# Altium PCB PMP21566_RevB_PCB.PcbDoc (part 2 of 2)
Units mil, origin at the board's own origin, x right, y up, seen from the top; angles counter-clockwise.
Board outline 4339 x 2011 mil, 4 copper layers (Top Layer1, Layer2, Layer3, Bottom Layer4), stack 60.4 mil thick; 97 components, 43 nets, 239 pads, 687 vias.
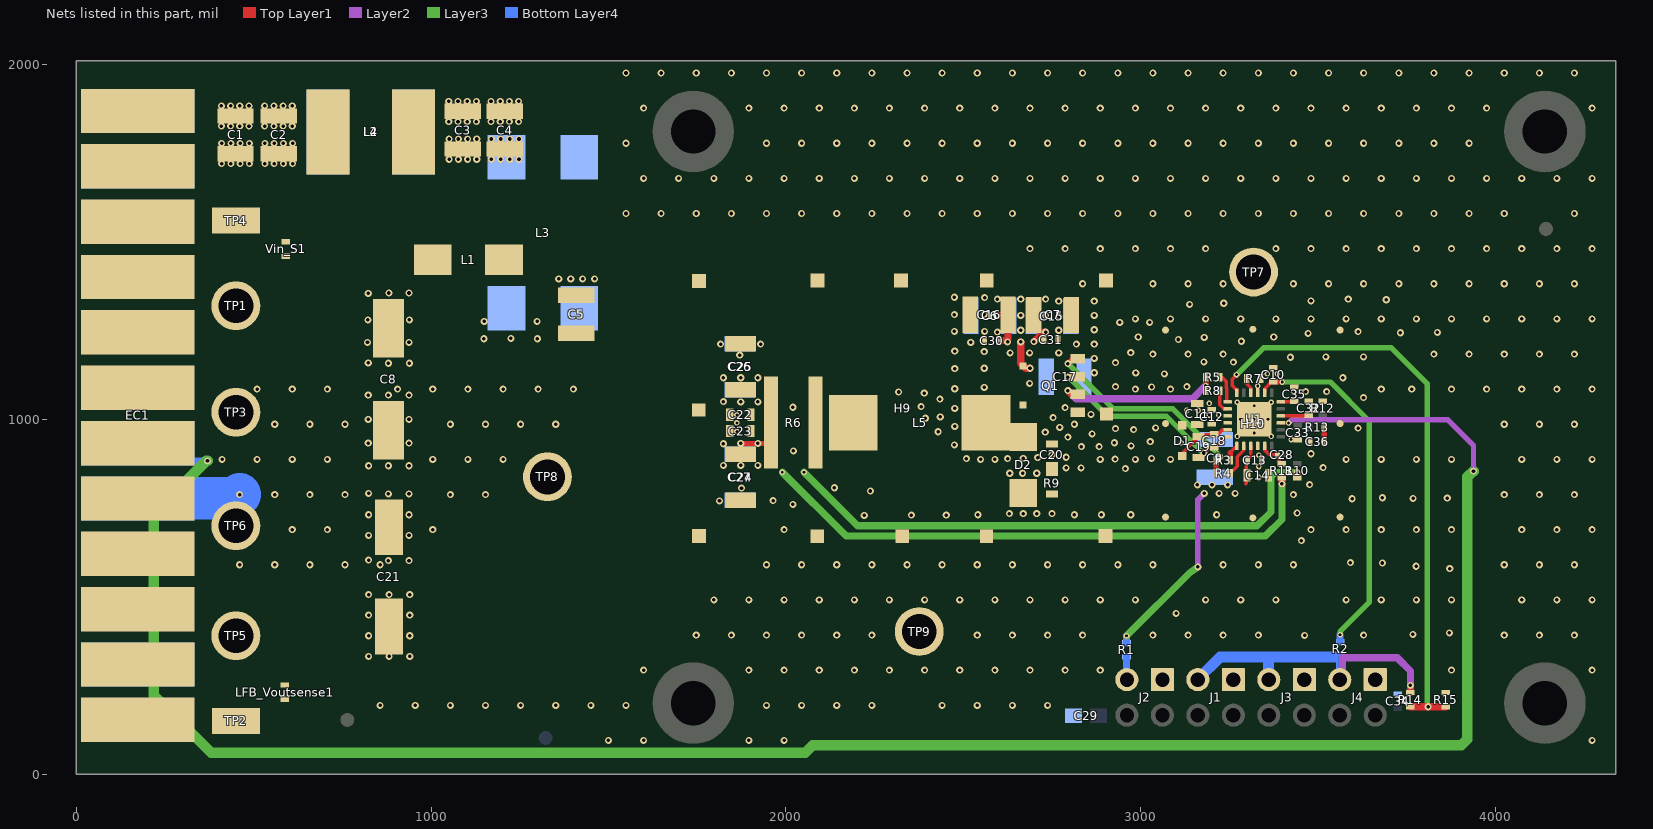
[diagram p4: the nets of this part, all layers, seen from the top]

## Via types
v1: diameter 20, hole 10, Top Layer1 to Bottom Layer4, tented both sides, 647 vias
v2: diameter 16, hole 8, Top Layer1 to Bottom Layer4, tented both sides, 35 vias
v3: diameter 19.68, hole 7.87, Top Layer1 to Bottom Layer4, 5 vias

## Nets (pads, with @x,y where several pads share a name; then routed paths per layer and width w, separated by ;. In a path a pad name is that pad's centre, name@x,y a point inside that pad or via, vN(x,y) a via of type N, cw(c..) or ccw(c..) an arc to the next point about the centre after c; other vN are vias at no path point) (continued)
GND: C5.2 C6.2 C7.2 C8.2 C9.2 C10.1 C11.2 C12.1 C13.2 C14.2 C15.2 C16.2 C17.2 C21.2 C22.2 C23.2 C24.2 C25.2 C26.2 C27.2 C29.2 C30.2 C31.2 C32.2 C33.2 C34.1 C35.2 C36.2 D2.2 EC1.5 EC1.D EC1.E EC1.F EC1.H H9.1 H10.1 J1.1 J2.1 J3.1 J4.1 L3.3 Q1.1 R7.2 R9.1 R12.1 R15.2 TP3.1 TP6.1 TP7.1 TP8.1 TP9.1 U1.3 U1.9 U1.16 U1.25@3320,1000 | length 292.1
  Bottom Layer4 w120: EC1.5@173,777 449.5,777 v1(460.5,788)
  other v1: 1500,95 1599,95 1896,95 1995,95 4272,95 856.5,194 955.5,194 1054.5,194 1153.5,194 1252.5,194 1351.5,194 1450.5,194 1549.5,194 1945.5,194 2044.5,194 2143.5,194 2242.5,194 2440.5,194 2539.5,194 2638.5,194 2737.5,194 1599,293 1896,293 1995,293 2094,293 2193,293 2292,293 2391,293 2490,293 2589,293 2688,293 2787,293 2886,293 3876,293 4272,293 3462,391 1747.5,392 1846.5,392 1945.5,392 2044.5,392 2143.5,392 2242.5,392 2539.5,392 2638.5,392 2737.5,392 2836.5,392 3034.5,392 3133.5,392 3232.5,392 3331.5,392 3628.5,392 4024.5,392 4123.5,392 4222.5,392 3767,394 3870,398 3100,453 1797,491 1896,491 1995,491 2094,491 2193,491 2292,491 2391,491 2490,491 2589,491 2688,491 2787,491 2886,491 2985,491 3183,491 3282,491 3381,491 3579,491 3678,491 3777,491 3876,491 4074,491 4173,491 4272,491 3871,579 3776,586 460.5,590 559.5,590 658.5,590 757.5,590 856.5,590 1945.5,590 2044.5,590 2143.5,590 2242.5,590 2341.5,590 2440.5,590 2539.5,590 2638.5,590 2737.5,590 2836.5,590 2935.5,590 3034.5,590 3232.5,590 3331.5,590 3430.5,590 4024.5,590 4123.5,590 4222.5,590 3681,595 3591,596 880,602 938,602 824,603 3453,658 824,673 938,673 609,689 708,689 1005,689 1995,689 3480,689 3579,689 3678,689 3777,689 3876,689 4074,689 4173,689 4272,689 2221,729 2354,730 2452,730 824,731 938,731 2541,731 2813,731 2889,731 2972,731 3214,731 2630,734 2669,734 2707,734 2750,734 3441,736 2020,760 1813,770 1964,771 3596,776 3768,777 3864,778 3681,779 559.5,788 658.5,788 757.5,788 1054.5,788 1153.5,788 3430.5,788 4024.5,788 4123.5,788 4222.5,788 880,790 938,790 824,791 2238,798 1875,806 2137,807 3476,816 2631,848 2667,848 2707,848 2957,861 2790,863 2832,863 3514,864 824,869 880,869 938,869 411,887 510,887 609,887 708,887 1005,887 1104,887 1203,887 2549,887 2589,887 2886,887 2985,887 3084,887 3579,887 3678,887 3777,887 3876,887 4074,887 4173,887 4272,887 2928,888 2509,889 2625,889 2669,890 3031,890 2710,892 2790,893 2750,900 3480,903 2021,911 2833,923 2883,923 2973,925 2475,928 823,933 938,933 2926,934 3027,937 2795,950 2863,959 2731,964 2429,965 2980,971 2929,974 3613,975 3042,976 2772,977 2476,980 559.5,986 658.5,986 757.5,986 1054.5,986 1153.5,986 1252.5,986 1351.5,986 2813,986 4024.5,986 4123.5,986 4222.5,986 823,1000 938,1000 2393,1003 2753,1005 2435,1007 2860,1014 2476,1031 2787,1033 2020,1034 2381,1036 2434,1057 3628,1061 823,1068 880,1068 938,1068 2390,1074 2318,1077 3465,1078 3524,1078 510,1085 609,1085 708,1085 906,1085 1005,1085 1104,1085 1203,1085 1302,1085 1401,1085 2985,1085 3084,1085 3678,1085 3764,1085 3876,1085 3975,1085 4074,1085 4173,1085 4272,1085 2476,1086 2559,1090 3031,1091 2929,1092 3130,1092 3570,1117 3067,1128 2869,1131.33 2986,1131 2476,1143 2559,1144 2929,1160 3261,1161 3178,1162 2869,1171.67 3422,1175 3522,1176 3628,1176 1870,1181 3034.5,1184 3133.5,1184 3232.5,1184 3826.5,1184 3925.5,1184 4024.5,1184 4123.5,1184 4222.5,1184 2769,1187 2972,1188 2559,1191 2476,1192 1816,1212 1929,1212 2819,1212 2869,1212 2521,1217 3284,1220 3106,1225 1149,1227 1300,1227 1225,1228 3179,1231 2993,1232 3375,1232 3472,1242 3732,1244 3836,1245 3613,1247 2475,1248 2560,1248 2769,1251 2869,1252.33 2941,1273 3025,1273 1150,1276 1299,1276 2985,1283 3084,1283 3183,1283 3282,1283 3381,1283 3480,1283 3579,1283 3678,1283 3777,1283 3876,1283 3975,1283 4074,1283 4173,1283 4272,1283 2769,1290 2869,1292.67 2475,1295 2559,1296 3138,1324 3234,1327 2769,1333 2869,1333 3480,1334 3692,1337 3585,1339 2560,1343 2475,1344 2836.5,1382 3034.5,1382 3133.5,1382 3232.5,1382 3430.5,1382 3529.5,1382 3628.5,1382 3727.5,1382 3826.5,1382 3925.5,1382 4024.5,1382 4123.5,1382 4222.5,1382 2688,1481 2787,1481 2886,1481 2985,1481 3084,1481 3183,1481 3381,1481 3480,1481 3579,1481 3678,1481 3777,1481 3876,1481 3975,1481 4074,1481 4173,1481 4272,1481 1549.5,1580 1648.5,1580 1747.5,1580 1846.5,1580 1945.5,1580 2044.5,1580 2143.5,1580 2242.5,1580 2341.5,1580 2440.5,1580 2539.5,1580 2638.5,1580 2737.5,1580 2836.5,1580 2935.5,1580 3034.5,1580 3133.5,1580 3232.5,1580 3331.5,1580 3430.5,1580 3529.5,1580 3628.5,1580 3727.5,1580 3826.5,1580 3925.5,1580 4024.5,1580 4222.5,1580 1599,1679 1698,1679 1797,1679 1896,1679 1995,1679 2094,1679 2193,1679 2292,1679 2391,1679 2490,1679 2589,1679 2688,1679 2787,1679 2886,1679 2985,1679 3084,1679 3183,1679 3282,1679 3381,1679 3480,1679 3579,1679 3678,1679 3777,1679 3876,1679 3975,1679 4074,1679 4173,1679 4272,1679 1549.5,1778 1945.5,1778 2044.5,1778 2143.5,1778 2242.5,1778 2341.5,1778 2440.5,1778 2539.5,1778 2638.5,1778 2737.5,1778 2836.5,1778 2935.5,1778 3034.5,1778 3133.5,1778 3232.5,1778 3331.5,1778 3430.5,1778 3529.5,1778 3628.5,1778 3727.5,1778 3826.5,1778 3925.5,1778 1599,1877 1896,1877 1995,1877 2094,1877 2193,1877 2292,1877 2391,1877 2490,1877 2589,1877 2688,1877 2787,1877 2886,1877 2985,1877 3084,1877 3183,1877 3282,1877 3381,1877 3480,1877 3579,1877 3678,1877 3777,1877 3876,1877 3975,1877 4272,1877 1549.5,1976 1648.5,1976 1747.5,1976 1846.5,1976 1945.5,1976 2044.5,1976 2143.5,1976 2242.5,1976 2341.5,1976 2440.5,1976 2539.5,1976 2638.5,1976 2737.5,1976 2836.5,1976 2935.5,1976 3034.5,1976 3133.5,1976 3232.5,1976 3331.5,1976 3430.5,1976 3529.5,1976 3628.5,1976 3727.5,1976 3826.5,1976 3925.5,1976 4024.5,1976 4123.5,1976 4222.5,1976
  other v2: 3333,836 3333,867 3333,899 3114,934 3424,943 3272,952 3368,952 3443,957 1862,966 1862,990 1862,1012 3193,1012 3220,1012 3130,1025 3162,1025 3193,1045 3272,1048 3368,1048 3431,1078 3330,1094 3357,1128 3385,1128
  other v3: 3320,961.61 3281.61,1000 3320,1000 3358.39,1000 3320,1038.39
Gnd_EMI: C1.2 C2.1 EC1.11 EC1.12 L2.1
  other v1: 410,1720.49 436,1720.49 462,1720.49 488,1720.49 410,1777.49 436,1777.49 462,1777.49 488,1777.49 531,1826.49 557,1826.49 583,1826.49 609,1826.49 531,1883.49 557,1883.49 583,1883.49 609,1883.49
HB: C18.1 C19.2 D1.1 U1.11 | length 164
  Top Layer1 w10: D1.1@3117,895.69 3117,904 3170,957 3217,957 3230.47,970.47 U1.11@3245.2,970.47
HO: R3.1 U1.13 | length 47
  Top Layer1 w10: 3252,906.41 U1.13@3270.79,925.2
  Top Layer1 w15: R3.1@3252,886 3252,906.41
HOL: R4.1 U1.14 | length 93.1
  Top Layer1 w10: R4.1@3252,848 3272,868 3272,894.63 3290.47,913.1 U1.14@3290.47,925.2
HS: Q1.4 R3.2 R4.2 | length 629
  Top Layer1 w15: v1(2795,1157) 2808.26,1170.26 Q1.4@2822.87,1170.26 ; R4.2@3212,848 R3.2@3212,885 3217,885 v2(3226,894) ; R3.2@3212,886 R3.2@3212,887
  Layer3 w15: v1(2795,1157) 2922,1030 3090,1030 v2(3226,894)
LO: R8.1 U1.8 | length 60.6
  Top Layer1 w10: R8.1@3222.39,1074 3222.39,1040.89 3233.75,1029.53 U1.8@3245.2,1029.53
LOL: R5.1 U1.7 | length 81.7
  Top Layer1 w10: R5.1@3223,1117 3231,1117 3241.5,1106.5 3241.5,1089 3242,1088.5 3242,1052.41 U1.7@3245.2,1049.21
LS: Q1.2 R5.2 R8.2 | length 484.2
  Top Layer1 w15: R8.2@3183,1078 R8.2@3183,1080 v2(3183,1095) R5.2@3183,1117
  Top Layer1 w20: v1(2795,1081) 2805.74,1070.26 Q1.2@2822.87,1070.26
  Layer2 w20: v1(2795,1081) 2818,1058 3146,1058 v2(3183,1095)
NetC3_1: C3.1 C4.2 L2.2 L3.2
  other v1: 1170,1733 1196,1733 1222,1733 1248,1733 1170,1790 1196,1790 1222,1790 1248,1790 1050,1839 1076,1839 1102,1839 1128,1839 1050,1896 1076,1896 1102,1896 1128,1896
NetC3_2: C3.2 C4.1 L3.1 L4.2
  other v1: 1051,1733 1077,1733 1103,1733 1129,1733 1051,1790 1077,1790 1103,1790 1129,1790 1169,1839 1195,1839 1221,1839 1247,1839 1169,1896 1195,1896 1221,1896 1247,1896
NetC5_1: C5.1 L1.1 L3.4 | length 20.9
  Top Layer1 w10: C5.1@1388.15,1349.15 C5.1@1409,1349.15
  other v1: 1360,1396 1393.67,1396 1427.33,1396 1461,1396
NetC20_2: C20.2 R9.2
NetC36_1: C36.1 R13.1 | length 40
  Top Layer1 w15: C36.1@3517,937 R13.1@3517,977
NetL5_2: L5.2 R6.1 R10.1 | length 1636.7
  Top Layer1 w15: R6.1@2083.99,937.99 R6.1@2083.99,991
  Top Layer1 w20: R10.1@3441,839 v1(3441,850)
  Layer3 w20: v2(2051,851) 2202,700 3328,700 3367,739 3367,838 3379,850 v1(3441,850)
OSC: R14.1 R15.1 U1.6 | length 1686.3
  Top Layer1 w10: v2(3270,1126) 3270,1125 3258,1113 3258,1095.13 3268.13,1085 3269.1,1085 3270.79,1083.31 U1.6@3270.79,1074.8 U1.6@3270.79,1073.09
  Top Layer1 w20: R14.1@3760,190 v1(3810,190) R15.1@3860,190
  Layer3 w15: v2(3270,1126) 3271,1126 3347,1202 3706,1202 3808,1100 3808,192 v1(3810,190)
PG: EC1.6 U1.21 | length 6130.4
  Top Layer1 w10: U1.21@3394.8,990.16 3416.84,990.16 v2(3417,990)
  Layer2 w15: v2(3417,990) 3426,999 3865,999 3938,926 v1(3938,854)
  Layer3 w30: v1(370,883) 367,883 219,735 219,222 381,60 2055,60 2076,81 3903,81 3920,98 3920,838 v1(3938,854)
  Bottom Layer4 w20: EC1.6@182.76,933.04 232.79,883 v1(370,883)
RES: C35.1 U1.24 | length 36.2
  Top Layer1 w10: U1.24@3394.8,1049.21 C35.1@3431,1049.21
RT: R7.1 U1.4 | length 44.8
  Top Layer1 w10: R7.1@3299,1115 3299,1100.35 3310.16,1089.2 U1.4@3310.16,1074.8
SoftStart: C32.1 U1.22 | length 78.7
  Top Layer1 w10: U1.22@3394.8,1009.84 3471.84,1009.84 C32.1@3473,1011
SW: C18.2 C19.1 C20.1 D2.1 L5.1 Q1.3 Q1.6 U1.12 | length 578.2
  Top Layer1 w10: C18.2@3207,919 3238.79,950.79 U1.12@3245.2,950.79
  Top Layer1 w12: C19.1@3163,892 3165,892 v1(3178,905) 3192,919 C18.2@3207,919
  Layer3 w15: v1(2795,1119) 2797,1119 2907,1009 3072,1009 3176,905 v1(3178,905)
VCC: C11.1 C12.2 D1.2 U1.10
VDDA: C10.2 R2.2 U1.2 | length 1015.8
  Top Layer1 w10: U1.2@3349.53,1074.8 3349.53,1086.25 3368.27,1105 C10.2@3371,1105
  Top Layer1 w15: C10.2@3371,1105 v2(3399,1105)
  Layer3 w15: v2(3399,1105) 3535,1105 3644,996 3644,484.23 3562,402.23 v2(3562,393)
  Bottom Layer4 w20: R2.2@3562,373 v2(3562,393)
VDDA_R100K: J1.3 J3.3 J4.3 R2.1 R14.2 | length 889.1
  Top Layer1 w20: R14.2@3760,230 v1(3760,250)
  Layer2 w20: J4.3@3561.07,266.25 3568,273.18 3568,328 3723,328 3760,291 v1(3760,250)
  Layer3 w20: J4.3@3561.07,266.25 J4.3@3561.07,269.07
  Bottom Layer4 w20: J1.3@3161.07,266.25 J1.3@3161.07,267.07 ; J4.3@3561.07,266.25 R2.1@3561.07,330
  Bottom Layer4 w30: J1.3@3161.07,267.07 3224,330 3360,330 ; J3.3@3360,267.32 3360,330 ; R2.1@3561.07,330 3360,330
VIN: C6.1 C7.1 C8.1 C9.1 C13.1 C14.1 C15.1 C16.1 C17.1 C30.1 C31.1 EC1.J EC1.K L1.2 Q1.5 R1.2 TP1.1 U1.15 Vin_S1.2 | length 891.9
  Top Layer1 w10: 3296,818 3298,820 3298,884 3310.16,896.16 U1.15@3310.16,925.2
  Top Layer1 w20: v1(2595,1293) 2624.15,1293 C16.1@2626.15,1295 2626.15,1227.15 2621,1222 C30.1@2600,1222 ; v1(2662,1218) 2662,1157.11 Q1.5@2668.73,1150.38 2675.11,1144 v1(2688,1144) ; v1(2699,1219) 2726,1246 v1(2732,1246)
  Layer2 w16: v1(3161,584) 3161,773 v1(3179,791)
  Layer3 w20: v2(2960,390) 3137.31,567.31 v1(3161,584)
  Bottom Layer4 w20: R1.2@2960,370 v2(2960,390)
  other v1: 3221,791 3266,791 3160,815 3201,815 3245,815 2687,1101 880,1158 939,1158 823,1159 2632,1187 2687,1187 821,1217 938,1217 2625,1218 2596,1246 2662,1251 822,1280 939,1280 2662,1293 2732,1293 2596,1339 2662,1339 2732,1339 823,1355 881,1356 938,1356
Vin_EMI: C1.1 C2.2 EC1.M EC1.N L4.1
  other v1: 532,1720.49 558,1720.49 584,1720.49 610,1720.49 532,1777.49 558,1777.49 584,1777.49 610,1777.49 409,1826.49 435,1826.49 461,1826.49 487,1826.49 409,1883.49 435,1883.49 461,1883.49 487,1883.49
VIN_R100K: J2.3 R1.1 | length 70
  Bottom Layer4 w20: J2.3@2960,260 R1.1@2960,330
VINSENSE: EC1.L TP4.1 Vin_S1.1
Vo_IC: C28.2 R11.2 U1.17 | length 85.1
  Top Layer1 w10: U1.17@3349.53,925.2 3349.53,913.53 3363.06,900 3388.4,900 3388.98,899.42 3388.98,884.02 R11.2@3398,875
VOUT: C21.1 C22.1 C23.1 C24.1 C25.1 C26.1 C27.1 EC1.2 EC1.B EC1.C LFB_Voutsense1.1 R6.2 R11.1 TP5.1 | length 1706
  Top Layer1 w15: v1(1873,932) R6.2@1964,932
  Top Layer1 w20: v1(3398,818) R11.1@3398,831
  Layer3 w20: v2(1990,851) 2170,671 3351,671 3398,718 v1(3398,818)
  other v1: 824,332 882,332 940,332 824,390 940,390 824,448 940,448 824,506 882,506 940,506 1824,870 1873,870 1921,870 1824,931 1921,932 1873,1049 1921,1049 1824,1050 1824,1117 1873,1117 1921,1117
VOUTSENSE: EC1.A LFB_Voutsense1.2 TP2.1
pads on no net: FID1.1 FID2.1 FID3.1 FID4.1 H1.0 H2.0 H3.0 H4.0 H5.1 H6.1 H7.1 H8.1 LBL1.0 U1.25@3294.8,974.8 U1.25@3294.8,1025.2 U1.25@3345.2,974.8 U1.25@3345.2,1025.2

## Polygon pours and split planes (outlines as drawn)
VIN on Top Layer1 "VIN_L01_P100" (solid, pour order 100): 254,1465 694,1465 695,1466 694,1467 694,1622 1058,1622 1060,1620 1060,1157 254,1157
GND on Top Layer1 "GND_L01_P096" (solid, remove dead copper, pour order 96): 4324,2010 1538,2010 1525,1997 1525,-1 4322,-1 4324,1
VINSENSE on Top Layer1 "VINSENSE_L01_P088" (solid, remove dead copper, pour order 88): 330,1620 651,1620 651,1493 330,1493
GND on Top Layer1 "GND_L01_P084" (solid, remove dead copper, pour order 84): 253,1145 1567,1145 1567,0 831,0 831,559 253,559
VOUT on Top Layer1 "VOUT_L01_P032" (solid, remove dead copper, pour order 32): 1999.82,943 1813.83,943 1813.82,839 1999.82,839
VOUT on Top Layer1 "VOUT_L01_P034" (solid, remove dead copper, pour order 34): 2000,1142 1814,1142 1814,1038 2000,1038
NetL5_2 on Top Layer1 "NETL5_2_L01_P040" (solid, remove dead copper, pour order 40): 2040,1142 2040,839 2275.31,839 2275.31,1142
VOUT on Top Layer1 "VOUT_L01_P044" (solid, remove dead copper, pour order 44): 1878,1142 2000,1142 2000,840 1878,840
Vin_EMI on Top Layer1 "VIN_EMI_L01_P066" (solid, remove dead copper, pour order 66): 520,1790 770,1790 770,1650 520,1650
Vin_EMI on Top Layer1 "VIN_EMI_L01_P064" (solid, remove dead copper, pour order 64): 310,1930 500,1930 500,1820 310,1820
Vin_EMI on Top Layer1 "VIN_EMI_L01_P048" (solid, remove dead copper, pour order 48): 30,1930 390,1930 390,1650 30,1650
SW on Top Layer1 "SW_L01_P056" (solid, remove dead copper, pour order 56): 2828.98,1101.26 2828.98,1139.42 2758.76,1139.42 2748.98,1131.26 2748.98,1101.26 2585.07,1101.26 2585.07,981.26 2686.4,981.26 2788.98,1055.79 2788.98,1101.26
VIN on Top Layer1 "VIN_L01_P050" (solid, remove dead copper, pour order 50): 2585,1131.26 2742,1131.26 2742,1349 2585,1349
Gnd_EMI on Top Layer1 "GND_EMI_L01_P072" (solid, remove dead copper, pour order 72): 630,1930 390,1930 390,1650 630,1650
NetC3_1 on Top Layer1 "NETC3_1_L01_P052" (solid, remove dead copper, pour order 52): 1040,1930 1040,1690 1140,1690 1140,1930
NetC3_1 on Top Layer1 "NETC3_1_L01_P076" (solid, remove dead copper, pour order 76): 1260,1930 1040,1930 1040,1690 1260,1690
VCC on Top Layer1 "VCC_L01_P046" (solid, pour order 46): 3255,995 3106,995 3106,971 3255,971
VIN on Top Layer1 "VIN_L01_P008" (solid, pour order 8): 3315,801 3263,801 3263,880.84 3315,941.91
VIN on Top Layer1 "VIN_L01_P090" (solid, pour order 90): 3315,828 3150,828 3150,778 3270.49,778 3315,801
GND on Top Layer1 "GND_L01_P104" (solid, remove dead copper, pour order 104): 1561,1063 1561,1287 1031,1287 1031,1063
NetC5_1 on Top Layer1 "NETC5_1_L01_P106" (solid, pour order 106): 1140,1595 1480,1595 1480,1305 1140,1305
GND on Layer2 "GND_L02_P098" (solid, pour order 98): 1644,1627 42,1627 42,0 1644,0
GND on Layer2 "GND_L02_P078" (solid, remove dead copper, pour order 78): 1539,2011 4294,2011 4294,0 1539,0
Vin_EMI on Layer2 "VIN_EMI_L02_P060" (solid, remove dead copper, pour order 60): 630,1650 390,1650 390,1930 630,1930
NetC3_2 on Layer2 "NETC3_2_L02_P058" (solid, remove dead copper, pour order 58): 1030,1930 1030,1690 1260,1690 1260,1930
VIN on Layer3 "VIN_L03_P094" (solid, pour order 94): 347,1493 347,1110 1540,1110 1540,1493
VIN on Layer3 "VIN_L03_P092" (solid, pour order 92): 350,1462 350,1426 350,1181 995,1181 995,1462
GND on Layer3 "GND_L03_P080" (solid, pour order 80): 1529,2010 4331,2010 4339,2002 4339,19 1529,19
Gnd_EMI on Layer3 "GND_EMI_L03_P068" (solid, remove dead copper, pour order 68): 630,1930 390,1930 390,1650 630,1650
NetC3_1 on Layer3 "NETC3_1_L03_P074" (solid, remove dead copper, pour order 74): 1040,1930 1260,1930 1260,1690 1040,1690
VOUT on Layer3 "VOUT_L03_P012" (solid, remove dead copper, pour order 12): 1942,1138 1942,688 1496,242 329,242 329,564 964,564 1538,1138
VIN on Layer3 "VIN_L03_P022" (solid, pour order 22): 2750,1365 2750,1100 1975.37,1100 1713.91,1494 2621,1494
VIN on Layer3 "VIN_L03_P024" (solid, pour order 24): 2329,1493 1493,1493 1493,1148 1783,1148 1783.78,1148.78 2329,1150.26
VIN on Layer3 "VIN_L03_P002" (solid, pour order 2): 1947,1417 2523,841 3319,841 3319,752 2340,752 1947,1145
GND on Layer3 "GND_L03_P110" (solid, remove dead copper, pour order 110): 1415.01,1095 347,1095 347,571 1411.53,571
VOUT on Bottom Layer4 "VOUT_L04_P026" (solid, remove dead copper, pour order 26): 1010,527 1010,243 357,243 357,527
VOUT on Bottom Layer4 "VOUT_L04_P028" (solid, remove dead copper, pour order 28): 1010,371 1010,246 309,246 309,371
EN on Bottom Layer4 "EN_L04_P086" (solid, remove dead copper, pour order 86): 322,1619 402,1619 402,1494 322,1494
GND on Bottom Layer4 "GND_L04_P082" (solid, remove dead copper, pour order 82): 1662,1627 356,1627 356,559 1662,559
VOUT on Bottom Layer4 "VOUT_L04_P030" (solid, remove dead copper, pour order 30): 1931.88,943 1813,943 1813,858 1931.88,858
VOUT on Bottom Layer4 "VOUT_L04_P036" (solid, remove dead copper, pour order 36): 1931.73,1129 1814,1129 1814,1038 1931.73,1038
GND on Bottom Layer4 "GND_L04_P062" (solid, remove dead copper, pour order 62): 1530,0 4308.98,0 4308.98,1996 1530,1996
Vin_EMI on Bottom Layer4 "VIN_EMI_L04_P070" (solid, remove dead copper, pour order 70): 630,1650 390,1650 390,1930 630,1930
VIN on Bottom Layer4 "VIN_L04_P038" (solid, remove dead copper, pour order 38): 2751,1349 2577.93,1349 2577.93,1246.47 2681.56,1069 2751,1069
VIN on Bottom Layer4 "VIN_L04_P006" (solid, remove dead copper, pour order 6): 3259.41,856 3280.04,779.55 3149,779.55 3149,856
GND on Bottom Layer4 "GND_L04_P102" (solid, pour order 102): 359,660.66 359,0 1595,0 1595,660.66
NetC3_2 on Bottom Layer4 "NETC3_2_L04_P108" (solid, remove dead copper, pour order 108): 1262,1930 1025,1930 1025,1689 1263.85,1689

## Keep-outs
Keep-Out Layer:
  text ".Layer_Name" at 195,-1308.49 h60

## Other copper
Top Layer1:
  rectangle net NetC3_2: 980,1690 1140,1800
  region net SW: 2758.98,1071.26 2628.98,1071.26 2628.98,1041.26 2758.98,1041.26
  region net SW: 2638.98,1091.26 2585.07,1091.26 2585.07,1051.26 2638.98,1051.26
  region net VIN: 2668.98,1111.26 2585.07,1111.26 2585.07,1101.26 2668.98,1101.26
  region net SW: 2760,940 2680,940 2680,920 2760,920
  region net SW: 2708.98,1021.26 2628.98,1021.26 2628.98,981.26 2708.98,981.26
  region net VOUTSENSE: 705,215.26 322.98,215.26 322.98,90.26 705,90.26
  rectangle net NetC3_2: 1157,1829 1260,1930
  region net Gnd_EMI: 500,1787.49 452,1787.49 452,1710.49 500,1710.49
  region net Gnd_EMI: 446,1787.49 398,1787.49 398,1710.49 446,1710.49
  region net Vin_EMI: 500,1892.49 452,1892.49 452,1816.49 500,1816.49
  region net Vin_EMI: 446,1892.49 398,1892.49 398,1816.49 446,1816.49
  region net Vin_EMI: 622,1787.49 574,1787.49 574,1710.49 622,1710.49
  region net Vin_EMI: 568,1787.49 520,1787.49 520,1710.49 568,1710.49
  region net Gnd_EMI: 622,1892.49 574,1892.49 574,1816.49 622,1816.49
  region net Gnd_EMI: 568,1892.49 520,1892.49 520,1816.49 568,1816.49
  rectangle net NetC3_2: 1211,1829 1259,1906
  rectangle net NetC3_1: 1157,1724 1205,1800
  rectangle net NetC3_1: 1211,1724 1259,1800
  rectangle net NetC3_2: 1040,1690 1140,1800
  rectangle net NetC3_2: 1038,1724 1086,1800
  rectangle net NetC3_1: 1092,1829 1140,1906
  rectangle net NetC3_1: 1038,1829 1086,1906
  region net VOUT: 1010,527 253,527 253,246.26 1010,246.26
Bottom Layer4:
  rectangle net GND: 1130,1215 1312,1383
  rectangle net NetC5_1: 1339,1244 1480,1411
  rectangle net Gnd_EMI: 521,1810 680,1930
  rectangle net Gnd_EMI: 40,1650 380,1930
  rectangle net Gnd_EMI: 330,1650 497,1790
  rectangle net NetC3_1: 1000,1829 1138,1930
  rectangle net NetC3_2: 1160,1811 1408,1930
  rectangle net NetC3_2: 1348,1677 1478,1930

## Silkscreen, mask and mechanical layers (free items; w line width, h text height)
Top Overlay:
  lines w8: 2911.07,26.25 2911.07,116.25 ; 3111.07,26.25 3111.07,116.25 ; 3311.07,26.25 3311.07,116.25 ; 3511.07,26.25 3511.07,116.25 ; 3711.07,26.25 3711.07,116.25 3911.07,116.25 ; 3911.07,26.25 3911.07,316.25
  text "VIN EMI" at 370,1910 h80
  text "AUTOMOTIVE  EMI & THERMALY OPTIMIZED" at 2112,1836 h90
  text "EMI / Filter" at 1231,1749 h80
  text "2.1MHz / 440kHz WIDE VIN LM5141-Q1" at 2220,1740 h90
  text "Sin" at 550,1530 h72.83
  text "VIN" at 549,1303 h72.83
  text "60V / max." at 524,1115 h72.83
  text "GND" at 550,990 h72.83
  text "Vin" at 3251,798 h40
  text "GND" at 550,670 h72.83
  text "Power Stage" at 2150,560 h80
  text "LM5141-Q1" at 3134,560 h80
  text "VOUT" at 550,370 h72.83
  text "VIN" at 2931.07,326.25 h40
  text "GND" at 3021.07,326.25 h40
  text "VDDA" at 3111.07,326.25 h40
  text "GND" at 3221.07,326.25 h40
  text "VDDA" at 3311.07,326.25 h40
  text "GND" at 3421.07,326.25 h40
  text "VDDA" at 3521.07,326.25 h40
  text "GND" at 3631.07,326.25 h40
  text "VDDA" at 3721.07,326.25 h40
  text "GND" at 3831.07,326.25 h40
  text "Sout" at 550,130 h72.83
  text "ON" at 2930,80 h40
  text "OFF" at 3030,80 h40
  text "FPWM" at 3120,80 h40
  text "PFM" at 3230,80 h40
  text "3.3V" at 3330,80 h40
  text "5.0V" at 3420,80 h40
  text "OFF" at 3530,80 h40
  text "ON" at 3640,80 h40
  text "2.2M" at 3730,80 h40
  text "440k" at 3820,80 h40
  text "ENABLE" at 2941.07,36.25 h40
  text "OSC" at 3781.07,36.25 h40
  text "R. Loke Mar 2018" at 288,16 h72.83
Bottom Overlay:
  text "FB" at 3433,83 h40
  text "DITH" at 3651,82 h40
  text "DEMB" at 3261,80 h40
  text "ENABLE" at 3078,79 h40
Top Solder:
  rectangle: 3129,976 3192,995
  rectangle: 1814,949 1857,1032
  rectangle: 1884,928 1941,1057
  region: 2470,1112 2470,1260 2303,1260 2303,1112
  region: 2470,712 2470,860 2303,860 2303,712
  rectangle: 1132,1301 1310,1600
  rectangle: 960,1302 1064,1601
Bottom Solder:
  text ".Layer_Name" at 195,-1308.49 h60
Drill Guide:
  text ".Layer_Name" at 195,-1308.49 h60
M1 Board Outline:
  the board outline again, w10
  text ".Layer_Name" at 195,-1308.49 h60
M2 Board Dimensions:
  lines w7: -382,-725 618,-725 ; -382,-600 -382,-850 618,-850 ; -257,-850 -257,-600
  text ".Layer_Name" at 195,-1308.49 h60
M3 3D STEP Top:
  text ".Layer_Name" at 195,-1308.49 h60
M4 3D STEP Bottom:
  text ".Layer_Name" at 195,-1308.49 h60
M5 Assembly Top:
  lines w10: -674,-1380.17 5926,-1380.17 ; -674,-1176.83 5928,-1176.83 ; -674,-973.5 -674,-1583.5 3331,-1583.5 5928,-1583.5 5928,-973.5 -673.5,-973.5 -673.5,-1583.5 902,-1583.5 ; 1791,-1583.5 1791,-973.5 ; 3058,-1176.83 3058,-973.5 ; 3898,-1176.83 3898,-973.5 ; 4520,-1590 4520,-1387.17
  text "COMPONENTS MARKED 'DNP' SHOULD NOT BE POPULATED." at 771.5,-768.5 h60
  text "ASSEMBLY VARIANT:" at 771,-884 h60
  text ".VariantName" at 1807,-884 h60
  text "PCB VIEWED FROM TOP SIDE" at -610.5,-1105.67 h60
  text "BOARD #:" at 1866,-1105.67 h60
  text ".PRJ_Number" at 2411.5,-1105.67 h60
  text "REV:" at 3256,-1105.67 h60
  text ".PCB_Rev" at 3547.5,-1105.67 h60
  text "SVN REV:" at 4094,-1105.67 h60
  text ".VersionControl_RevNumber" at 4600,-1105.67 h60
  text "PLOT NAME =" at -610.5,-1514.34 h60
  text ".plot_File_Name" at 195,-1514.34 h60
  text "GENERATED    :" at 1868,-1514.34 h60
  text ".Print_Date" at 2737.5,-1514.34 h60
  text ".Print_Time" at 3466.5,-1514.34 h60
  text "TEXAS INSTRUMENTS" at 4731,-1514.34 h60
M6 Assembly Bottom:
  lines w10: -674.5,-1177.33 5927.5,-1177.33 ; -672.5,-1380.67 5927.5,-1380.67 ; 733.5,-1590.5 733.5,-1387.67 ; 1355.5,-1177.33 1355.5,-974 ; 2195.5,-1177.33 2195.5,-974 ; 3462.5,-1584 3462.5,-974 ; 4351.5,-1584 5927,-1584 5927,-974 -674.5,-974 -674.5,-1584 1922.5,-1584 5927.5,-1584 5927.5,-974
  text "COMPONENTS MARKED 'DNP' SHOULD NOT BE POPULATED." at 5720,-768 h60
  text ".VariantName" at 4676,-884 h60
  text "ASSEMBLY VARIANT:" at 5715,-884 h60
  text ".VersionControl_RevNumber" at 653.5,-1106.17 h60
  text "SVN REV:" at 1159.5,-1106.17 h60
  text ".PCB_Rev" at 1706,-1106.17 h60
  text "REV:" at 1997.5,-1106.17 h60
  text ".PRJ_Number" at 2842,-1106.17 h60
  text "BOARD #:" at 3387.5,-1106.17 h60
  text "PCB VIEWED FROM BOTTOM SIDE" at 5864,-1106.17 h60
  text "TEXAS INSTRUMENTS" at 522.5,-1514.84 h60
  text ".Print_Time" at 1787,-1514.84 h60
  text ".Print_Date" at 2516,-1514.84 h60
  text "GENERATED    :" at 3385.5,-1514.84 h60
  text ".plot_File_Name" at 5058.5,-1514.84 h60
  text "PLOT NAME =" at 5864,-1514.84 h60
M9 Title Sheet:
  drawing of 57 lines, arcs and shapes, not listed
  text "1" at 357.84,7586.5 h70
  text "2" at 2853.5,7586.5 h70
  text "3" at 5342.84,7586.5 h70
  text "4" at 7849.51,7586.5 h70
  text "5" at 10348.5,7586.5 h70
  text "6" at 12853.5,7586.5 h70
  text "A" at -798.5,6443.5 h70
  text "A" at 14001.5,6443.5 h70
  text "B" at -798.5,4063.5 h70
  text "B" at 14001.5,4063.5 h70
  text "C" at -798.5,1688.5 h70
  text "C" at 14001.5,1688.5 h70
  text "PROJECT TITLE:" at 10961.5,-172.5 h45
  text ".PRJ_Title" at 11011.5,-305.83 h70
  text "DESIGNED FOR:" at 10961.5,-473.5 h45
  text ".PRJ_Customer" at 11011.5,-613.5 h70
  text "D" at -798.5,-681.5 h70
  text "D" at 14001.5,-681.5 h70
  text "FILE NAME:" at 10961.5,-773.5 h45
  text ".PCB_File_Name_No_Path" at 11011.5,-893.5 h70
  text "Texas Instruments (TI) and/or its licensors do not warrant the accuracy or completeness of this specification" at 5992,-1055.34 h45
  text "ENGINEER:" at 10961.5,-1063.5 h45
  text "LAYOUT BY:" at 12466.5,-1063.5 h45
  text "or any information contained therein. TI and/or its licensors do not warrant that this design will meet" at 5947.01,-1168 h45
  text ".PRJ_Engineer" at 11011.5,-1218.49 h70
  text ".PCB_Layout" at 12517,-1218.49 h70
  text "the specifications, will be suitable for your application or fit for any particular purpose, or will operate in" at 5947.01,-1280.67 h45
  text ".Layer_Name" at 195,-1308.49 h60
  text "ALTIUM DESIGNER VERSION:" at 12466.5,-1373.5 h45
  text "an implementation. TI and/or its licensors do not warrant that the design is production worthy. You should" at 5947.01,-1393.33 h45
  text "completely validate and test your design implementation to confirm the system functionality for your application." at 5992,-1506 h45
  text ".print_Scale" at 11011.5,-1506.83 h70
  text ".Application_BuildNumber" at 12517,-1506.83 h70
  text "1" at 357.84,-1713.5 h70
  text "2" at 2853.5,-1713.5 h70
  text "3" at 5342.84,-1713.5 h70
  text "4" at 7849.51,-1713.5 h70
  text "5" at 10348.5,-1713.5 h70
  text "6" at 12853.5,-1713.5 h70
M10 Fab Notes:
  drawing of 185 lines, arcs and shapes, not listed
  text "DESIGN INFORMATION" at 11999.02,5460 h60
  text "MIN. TRACK WIDTH:" at 11354.46,5280 h60
  text "8" at 12450.7,5280 h60
  text "MIL" at 12605.46,5280 h60
  text "MIN. CLEARANCE:" at 11354.46,5148 h60
  text "0.2" at 12390.7,5148 h60
  text "mm" at 12605.46,5148 h60
  text "MIN. VIA PAD SIZE:" at 11354.46,5016 h60
  text "20" at 12420.71,5016 h60
  text "MIL" at 12605.46,5016 h60
  text "0.05mm (2MIL)" at 12049.46,4874.29 h60
  text "MINIMUM ANNULAR RING" at 11025.23,4870 h60
  text "EXTERNAL" at 12757.46,4870 h60
  text "PER" at 11225.23,4752 h60
  text "IPC-D-275 CLASS 2 LEVEL C" at 11445.23,4752 h60
  text "MIL, HOLES" at 12933.46,4639.71 h60
  text "+/-" at 12541,4639 h60
  text "+/-" at 13395,4639 h60
  text "REGISTRATION TOLERANCES:" at 11025.23,4634 h60
  text "METAL" at 12225,4634 h60
  text "5" at 12801.2,4634 h60
  text "3" at 13634.2,4634 h60
  text "MIL" at 13750.46,4634 h60
  text "MATERIAL:" at 10950.46,4424.54 h60
  text "FR-4 High Tg" at 11936.9,4284.21 h60
  text "FR-408" at 11371.46,4275.64 h60
  text "X" at 11783.46,4275.64 h60
  text "OTHER" at 12859.46,4275.64 h60
  text "62 MIL (1.6mm) +/-10%" at 11691.56,4112.92 h60
  text "THICKNESS:" at 11025.23,4108.64 h60
  text "X" at 11563.4,4108.64 h60
  text "OTHER" at 12976.46,4108.64 h60
  text "TOLERANCE:" at 11025.23,3950.64 h60
  text "X" at 11864.53,3950.64 h60
  text "ANSI IPC-6012 TYPE 3 CLASS 2" at 12051.48,3950.64 h60
  text "OTHER +/-" at 12051.46,3794.64 h60
  text "BOW & TWIST:" at 11025.23,3637.64 h60
  text "X" at 11864.53,3637.64 h60
  text "ANSI IPC-6012 TYPE 3 CLASS 2" at 12051.48,3637.64 h60
  text "OTHER +/-" at 12051.46,3479.13 h60
  text "DRILLING:" at 10950.46,3340.64 h60
  text "REFERENCE:" at 11025.23,3223.64 h60
  text "X" at 11673.46,3223.64 h60
  text "AS SHOWN" at 11860.46,3223.64 h60
  text "X" at 12574.46,3223.64 h60
  text "NC_DRILL FILES" at 12711.46,3223.64 h60
  text "PTH MIN COPPER THICKNESS:" at 11025.23,3065.64 h60
  text "X" at 12375.46,3065.64 h60
  text "1MIL" at 12512.46,3065.64 h60
  text "OTHER" at 13009.46,3065.64 h60
  text "BOARD FINISH:" at 10950.46,2906.64 h60
  text "SILKSCREEN:" at 11105.68,2788.64 h60
  text "X" at 12054.46,2788.64 h60
  text "TOP" at 12180.46,2788.64 h60
  text "X" at 12564.46,2788.64 h60
  text "BOTTOM" at 12691.46,2788.64 h60
  text "SILKSCREEN COLOR:" at 11105.68,2621.64 h60
  text "X" at 12053.42,2621.64 h60
  text "WHITE" at 12180.46,2621.64 h60
  text "OTHER" at 12691.46,2621.64 h60
  text "SOLDER RESIST COLOR:" at 11105.68,2451.64 h60
  text "GREEN" at 11800.46,2292.44 h60
  text "BLUE" at 12391.46,2292.44 h60
  text "OTHER" at 12929.46,2292.44 h60
  text "X" at 11670,2290 h60
  text "IMMERSION GOLD (ENIG)" at 12011.46,2103.92 h60
  text "ENEPIG" at 13349,2100.64 h60
  text "SURFACE FINISH:" at 10950.46,2099.64 h60
  text "X" at 11824.51,2099.64 h60
  text "IMM. TIN/SILVER OR EQUIV" at 11280,1942.64 h60
  text "OTHER" at 12711.46,1942.64 h60
  text "ARRAY/PANEL:" at 10950.46,1763.64 h60
  text "X" at 11820,1760 h60
  text "CUT AND TRIM PER MECH LAYER 1" at 12011.46,1759.35 h60
  text "N.C. ROUTE" at 12011.46,1607.64 h60
  text "V. SCORE" at 12877.46,1607.64 h60
  text "CERTIFICATION:" at 10950.46,1470.64 h60
  text "MATERIALS AND WORKMANSHIP FOR ALL PCBS" at 11675.46,1470.64 h60
  text "TO MEET OR EXCEED THE REQUIREMENTS OF:" at 11675.46,1372.64 h60
  text "X" at 11301.96,1236.13 h60
  text "ANSI IPC-A-600F CLASS ->" at 11440.96,1236.13 h60
  text "X" at 13080.02,1236.13 h60
  text "2" at 13198.96,1236.14 h60
  text "1" at 12883.96,1234.64 h60
  text "3" at 13552.96,1234.64 h60
  text "X" at 11304.02,1076.64 h60
  text "UL 94V-0" at 11440.96,1076.64 h60
  text "X" at 12116.02,1076.64 h60
  text "RoHS" at 12252.96,1076.64 h60
  text "OTHER" at 12897.36,1076.64 h60
  text "PER ORDER" at 13294.42,1076.64 h60
  text "ADDITIONAL REQUIREMENTS:" at 10950.46,935.64 h60
  text "MICROSECTION:" at 11025.23,820.64 h60
  text "YES" at 11930.96,820.64 h60
  text "REQUIRED" at 12792.46,664.49 h60
  text "BARE BOARD ELEC. TEST:" at 11025.23,661.64 h60
  text "NONE" at 12330.96,661.64 h60
  text "PER ORDER" at 13384.46,661.64 h60
  text "X" at 13260,660 h60
  text "MANUFACTURER'S UL:" at 11025.23,504.64 h60
  text "RAIL" at 12190.96,500.35 h60
  text "METAL" at 12682.77,500.35 h60
  text "X" at 13058,500 h60
  text "SILK" at 13194.46,500.35 h60
  text ".Layer_Name" at 195,-1308.49 h60
M11 Gerber Information:
  lines w10: -674,-1380.17 5926,-1380.17 ; -674,-1176.83 5928,-1176.83 ; -674,-973.5 -674,-1583.5 3331,-1583.5 5928,-1583.5 5928,-973.5 -673.5,-973.5 -673.5,-1583.5 902,-1583.5 ; 1791,-1583.5 1791,-973.5 ; 3058,-1176.83 3058,-973.5 ; 3898,-1176.83 3898,-973.5 ; 4520,-1590 4520,-1387.17
  text "ALL ARTWORK VIEWED FROM TOP SIDE" at -610.5,-1105.67 h60
  text "BOARD #:" at 1866,-1105.67 h60
  text ".PRJ_Number" at 2411.5,-1105.67 h60
  text "REV:" at 3256,-1105.67 h60
  text ".PCB_Rev" at 3547.5,-1105.67 h60
  text "SVN REV:" at 4094,-1105.67 h60
  text ".VersionControl_RevNumber" at 4600,-1105.67 h60
  text "LAYER NAME =" at -610.5,-1308.49 h60
  text "PLOT NAME =" at -610.5,-1514.34 h60
  text ".plot_File_Name" at 195,-1514.34 h60
  text "GENERATED    :" at 1868,-1514.34 h60
  text ".Print_Date" at 2737.5,-1514.34 h60
  text ".Print_Time" at 3466.5,-1514.34 h60
  text "TEXAS INSTRUMENTS" at 4731,-1514.34 h60
M12 Stackup:
  drawing of 295 lines, arcs and shapes, not listed
  text "Layer" at 6136.58,4798.78 h60
  text "Name" at 6546.49,4798.78 h60
  text "Material" at 7476.23,4798.78 h60
  text "Thickness" at 8336,4798.78 h60
  text "Constant" at 8985.83,4798.78 h60
  text "Board Layer Stack" at 9555.7,4798.78 h60
  text "1" at 6136.58,4678.78 h60
  text "Top Overlay" at 6546.49,4678.78 h60
  text "2" at 6136.58,4558.78 h60
  text "Top Solder" at 6546.49,4558.78 h60
  text "Solder Resist" at 7476.23,4558.78 h60
  text "0.40mil" at 8336,4558.78 h60
  text "3.5" at 8985.83,4558.78 h60
  text "3" at 6136.58,4438.78 h60
  text "Top Layer1" at 6546.49,4438.78 h60
  text "Copper" at 7476.23,4438.78 h60
  text "2.80mil" at 8336,4438.78 h60
  text "4" at 6136.58,4318.78 h60
  text "Dielectric1" at 6546.49,4318.78 h60
  text "FR-4" at 7476.23,4318.78 h60
  text "5.00mil" at 8336,4318.78 h60
  text "4.2" at 8985.83,4318.78 h60
  text "5" at 6136.58,4198.78 h60
  text "Layer2" at 6546.49,4198.78 h60
  text "Copper" at 7476.23,4198.78 h60
  text "1.40mil" at 8336,4198.78 h60
  text "6" at 6136.58,4078.78 h60
  text "Dielectric 3" at 6546.49,4078.78 h60
  text "FR4" at 7476.23,4078.78 h60
  text "42.00mil" at 8336,4078.78 h60
  text "4.2" at 8985.83,4078.78 h60
  text "7" at 6136.58,3958.78 h60
  text "Layer3" at 6546.49,3958.78 h60
  text "Copper" at 7476.23,3958.78 h60
  text "1.40mil" at 8336,3958.78 h60
  text "8" at 6136.58,3838.78 h60
  text "Dielectric 2" at 6546.49,3838.78 h60
  text "FR4" at 7476.23,3838.78 h60
  text "5.00mil" at 8336,3838.78 h60
  text "4.2" at 8985.83,3838.78 h60
  text "9" at 6136.58,3718.78 h60
  text "Bottom Layer4" at 6546.49,3718.78 h60
  text "Copper" at 7476.23,3718.78 h60
  text "2.80mil" at 8336,3718.78 h60
  text "10" at 6136.58,3598.78 h60
  text "Bottom Solder" at 6546.49,3598.78 h60
  text "Solder Resist" at 7476.23,3598.78 h60
  text "0.40mil" at 8336,3598.78 h60
  text "3.5" at 8985.83,3598.78 h60
  text "11" at 6136.58,3478.78 h60
  text "Bottom Overlay" at 6546.49,3478.78 h60
  text ".Layer_Name" at 195,-1308.49 h60
M13 Component Bodies Top:
  text ".Layer_Name" at 195,-1308.49 h60
M14 Component Bodies Bottom:
  text ".Layer_Name" at 195,-1308.49 h60
M15 Courtyards Top:
  text ".Layer_Name" at 195,-1308.49 h60
M16 Courtyards Bottom:
  text ".Layer_Name" at 195,-1308.49 h60
Drill Drawing:
  circle w10: c4543.72,1672.96 r16.58
  circle w10: c4543.72,1672.96 r27.63
  circle w10: c4543.72,1175.68 r27.63
  lines w10: 4516.09,1286.19 4529.9,1286.19 4529.9,1272.38 4557.53,1272.38 4557.53,1286.19 4571.34,1286.19 4571.34,1313.82 4557.53,1313.82 4557.53,1327.63 4529.9,1327.63 4529.9,1313.82 4516.09,1313.82 4516.09,1286.19 ; 4516.09,1451.95 4571.34,1451.95 4543.72,1396.7 4516.09,1451.95 ; 4516.09,1534.83 4529.9,1534.83 4543.72,1521.02 4557.53,1534.83 4571.34,1534.83 4557.53,1548.64 4571.34,1562.46 4557.53,1562.46 4543.72,1576.27 4529.9,1562.46 4516.09,1562.46 4529.9,1548.64 4516.09,1534.83 ; 4516.09,1797.28 4543.72,1769.66 4571.34,1797.28 4543.72,1824.91 4516.09,1797.28
  lines w12: 4466,1110.76 6444.02,1110.76 ; 4466,1856.68 6444.02,1856.68 ; 4803.86,986.44 4803.86,1981 ; 5135.86,986.44 5135.86,1981 ; 5772.43,986.44 5772.43,1981 ; 6031.57,986.44 6031.57,1981 ; 4466,986.44 6444.02,986.44 6444.02,1981 4466,1981 4466,986.44
  text "Symbol" at 4540.59,1893.98 h72
  text "Quantity" at 4841.16,1893.98 h72
  text "Finished Hole Size" at 5173.16,1893.98 h72
  text "Plated" at 5809.72,1893.98 h72
  text "Hole Type" at 6068.86,1893.98 h72
  text "5" at 4841.16,1769.66 h60
  text "7.87mil (0.200mm)" at 5173.16,1769.66 h60
  text "PTH" at 5809.72,1769.66 h60
  text "Round" at 6068.86,1769.66 h60
  text "35" at 4841.16,1645.34 h60
  text "8.00mil (0.203mm)" at 5173.16,1645.34 h60
  text "PTH" at 5809.72,1645.34 h60
  text "Round" at 6068.86,1645.34 h60
  text "647" at 4841.16,1521.02 h60
  text "10.00mil (0.254mm)" at 5173.16,1521.02 h60
  text "PTH" at 5809.72,1521.02 h60
  text "Round" at 6068.86,1521.02 h60
  text "16" at 4841.16,1396.7 h60
  text "40.00mil (1.016mm)" at 5173.16,1396.7 h60
  text "PTH" at 5809.72,1396.7 h60
  text "Round" at 6068.86,1396.7 h60
  text "7" at 4841.16,1272.38 h60
  text "98.43mil (2.500mm)" at 5173.16,1272.38 h60
  text "PTH" at 5809.72,1272.38 h60
  text "Round" at 6068.86,1272.38 h60
  text "4" at 4841.16,1148.06 h60
  text "125.00mil (3.175mm)" at 5173.16,1148.06 h60
  text "PTH" at 5809.72,1148.06 h60
  text "Round" at 6068.86,1148.06 h60
  text "714 Total" at 4841.16,1023.74 h60
  text ".Layer_Name" at 195,-1308.49 h60

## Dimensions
-7,2030 to 4338.98,2011.26 on M2 Board Dimensions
